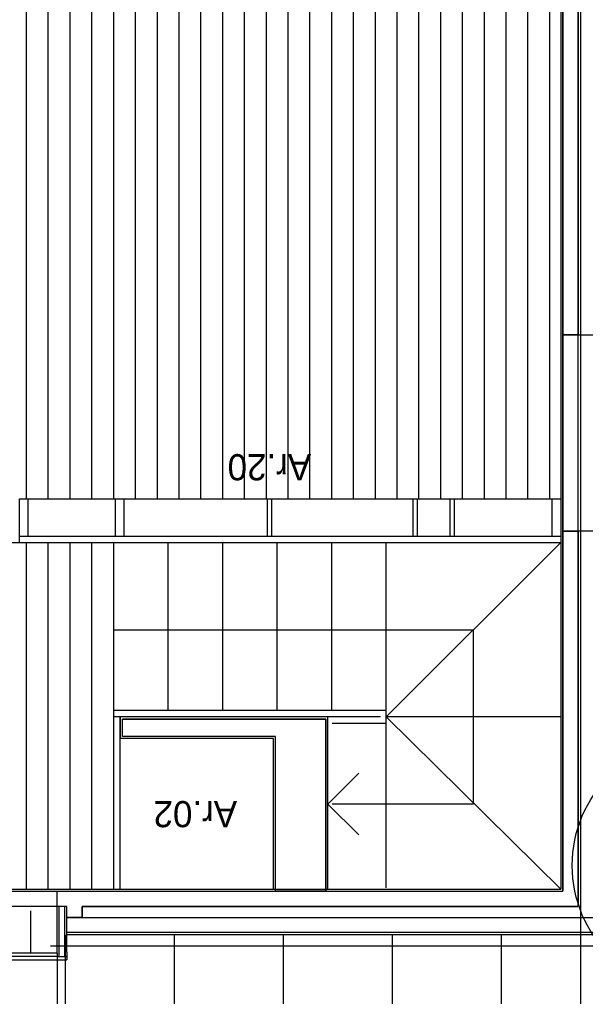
# Model space of a CAD drawing. Extents: x 1248 to 1356, y -443 to -224.
# Drawn here: x 1321.309 to 1323.905, y -238.907 to -234.424 of the extents above; entities that cross this region are included whole.
import ezdxf

# ---------------------------------------------------------------- set-up
doc = ezdxf.new("R2010")
doc.units = 0
for name, color, linetype in [('corte', 7, 'Continuous'), ('estereoctomias', 7, 'Continuous'), ('ind-pormenores', 7, 'Continuous'), ('Level 1', 7, 'Continuous'), ('Level 10', 7, 'Continuous'), ('Level 13', 7, 'Continuous'), ('Level 2', 7, 'Continuous'), ('Level 4', 7, 'Continuous'), ('Level 40', 7, 'Continuous'), ('revestimentos', 7, 'Continuous'), ('vermelhos-cont', 7, 'Continuous')]:
    doc.layers.add(name, color=color, linetype=linetype)

msp = doc.modelspace()

# ---------------------------------------------------------------- linework, layer by layer
at = {"layer": 'corte'}
for p, q in [((1323.871, -236.7713), (1323.871, -232.114)), ((1323.801, -238.424), (1323.801, -232.264)), ((1323.871, -238.494), (1323.871, -236.7713)), ((1320.616, -238.424), (1323.801, -238.424)), ((1321.596, -238.494), (1323.871, -238.494)), ((1321.596, -238.544), (1325.0318, -238.544)), ((1325.1368, -238.614), (1321.526, -238.614))]:
    msp.add_line(p, q, dxfattribs=at)
msp.add_lwpolyline([(1323.801, -235.8713), (1324.031, -235.8713), (1324.031, -236.7713), (1323.801, -236.7713)], close=True, dxfattribs=at)
at = {"layer": 'estereoctomias'}
for points in [[(1323.871, -232.264), (1323.871, -235.8713), (1323.801, -235.8713), (1323.801, -232.264)], [(1321.596, -238.494), (1321.596, -238.544), (1321.526, -238.544), (1321.526, -238.494), (1320.686, -238.494), (1320.686, -238.709), (1320.616, -238.709), (1320.616, -238.424), (1323.801, -238.424), (1323.801, -236.7713), (1323.871, -236.7713), (1323.871, -238.494)], [(1321.781, -237.634), (1322.7136, -237.634), (1322.7136, -238.424), (1322.4836, -238.424), (1322.4836, -237.714), (1321.781, -237.714)], [(1325.1368, -238.544), (1325.1368, -238.614), (1321.526, -238.614), (1321.526, -238.544), (1325.1368, -238.544)]]:
    msp.add_lwpolyline(points, close=True, dxfattribs=at)
at = {"layer": 'ind-pormenores'}
msp.add_circle((1324.4286, -238.3059), 0.5842, dxfattribs=at)
at = {"layer": 'Level 1'}
for p, q in [((1323.801, -232.264), (1323.801, -238.424)), ((1321.781, -237.714), (1321.781, -237.634)), ((1322.7136, -237.634), (1321.781, -237.634)), ((1322.7136, -238.424), (1322.7136, -237.634)), ((1322.4836, -237.714), (1321.781, -237.714)), ((1322.4836, -238.424), (1322.4836, -237.714)), ((1321.526, -238.494), (1320.686, -238.494)), ((1321.526, -238.614), (1321.526, -238.494)), ((1321.596, -238.544), (1321.596, -238.494))]:
    msp.add_line(p, q, dxfattribs=at)
at = {"layer": 'Level 10'}
for p, q in [((1321.341, -236.624), (1321.341, -232.274)), ((1321.441, -236.624), (1321.441, -232.274)), ((1321.541, -236.624), (1321.541, -232.274)), ((1321.641, -236.624), (1321.641, -232.274)), ((1321.741, -236.624), (1321.741, -232.274)), ((1321.841, -236.624), (1321.841, -232.274)), ((1321.941, -236.624), (1321.941, -232.274)), ((1322.041, -236.624), (1322.041, -232.274)), ((1322.141, -236.624), (1322.141, -232.274)), ((1322.241, -236.624), (1322.241, -232.274)), ((1322.341, -236.624), (1322.341, -232.274)), ((1322.441, -236.624), (1322.441, -232.274)), ((1322.541, -236.624), (1322.541, -232.274)), ((1322.641, -236.624), (1322.641, -232.274)), ((1322.741, -236.624), (1322.741, -232.274)), ((1322.841, -236.624), (1322.841, -232.274)), ((1322.941, -236.624), (1322.941, -232.274)), ((1323.041, -236.624), (1323.041, -232.274)), ((1323.141, -236.624), (1323.141, -232.274)), ((1323.241, -236.624), (1323.241, -232.274)), ((1323.341, -236.624), (1323.341, -232.274)), ((1323.441, -236.624), (1323.441, -232.274)), ((1323.541, -236.624), (1323.541, -232.274)), ((1323.641, -236.624), (1323.641, -232.274)), ((1323.741, -236.624), (1323.741, -232.274)), ((1321.341, -238.414), (1321.341, -236.824)), ((1321.441, -238.414), (1321.441, -236.824)), ((1321.541, -238.414), (1321.541, -236.824)), ((1321.641, -238.414), (1321.641, -236.824)), ((1321.5183, -238.624), (1321.5183, -240.224)), ((1322.0183, -238.624), (1322.0183, -240.224)), ((1322.5183, -238.624), (1322.5183, -240.224)), ((1323.0183, -238.624), (1323.0183, -240.224)), ((1323.5183, -238.624), (1323.5183, -240.224)), ((1321.451, -238.674), (1325.0718, -238.674))]:
    msp.add_line(p, q, dxfattribs=at)
at = {"layer": 'Level 13'}
for p, q in [((1321.309, -236.824), (1321.309, -236.624)), ((1321.309, -236.624), (1323.791, -236.624)), ((1321.349, -236.794), (1321.349, -236.624)), ((1321.749, -236.794), (1321.749, -236.624)), ((1321.789, -236.794), (1321.789, -236.624)), ((1322.4463, -236.794), (1322.4463, -236.624)), ((1322.4663, -236.794), (1322.4663, -236.624)), ((1323.1137, -236.794), (1323.1137, -236.624)), ((1323.1337, -236.794), (1323.1337, -236.624)), ((1323.2837, -236.794), (1323.2837, -236.624)), ((1323.3037, -236.794), (1323.3037, -236.624)), ((1323.751, -236.624), (1323.751, -236.794)), ((1321.309, -236.794), (1323.791, -236.794)), ((1321.309, -236.824), (1323.791, -236.824)), ((1321.309, -236.824), (1323.791, -236.824)), ((1321.309, -236.824), (1323.791, -236.824)), ((1321.7376, -236.824), (1323.791, -236.824)), ((1321.741, -238.414), (1321.741, -237.624)), ((1321.771, -237.624), (1321.741, -237.624)), ((1321.771, -238.414), (1321.771, -237.624)), ((1321.481, -238.709), (1321.481, -238.494)), ((1321.491, -238.724), (1321.491, -238.494)), ((1321.516, -238.724), (1321.516, -238.494)), ((1321.526, -238.704), (1321.526, -238.614)), ((1321.481, -238.709), (1320.576, -238.709)), ((1321.481, -238.709), (1321.481, -238.724)), ((1321.526, -238.704), (1321.526, -238.724)), ((1321.481, -238.724), (1320.616, -238.724)), ((1321.481, -238.724), (1320.616, -238.724)), ((1321.481, -238.724), (1320.626, -238.724)), ((1321.481, -238.724), (1321.481, -238.739)), ((1321.481, -238.724), (1321.526, -238.724)), ((1321.481, -238.739), (1321.526, -238.739)), ((1321.526, -238.724), (1321.526, -238.739))]:
    msp.add_line(p, q, dxfattribs=at)
at = {"layer": 'Level 2'}
for p, q in [((1321.741, -237.624), (1321.741, -236.824)), ((1321.741, -237.624), (1321.741, -236.824)), ((1321.991, -237.594), (1321.991, -236.824)), ((1322.241, -237.594), (1322.241, -236.824)), ((1322.491, -237.594), (1322.491, -236.824)), ((1322.741, -237.594), (1322.741, -236.824)), ((1322.991, -237.594), (1322.991, -236.824)), ((1322.991, -237.624), (1323.791, -236.824)), ((1321.741, -237.224), (1323.391, -237.224)), ((1323.391, -238.024), (1323.391, -237.224)), ((1322.991, -237.594), (1321.741, -237.594)), ((1322.991, -237.654), (1322.991, -237.594)), ((1322.9651, -237.624), (1321.741, -237.624)), ((1323.791, -237.624), (1322.991, -237.624)), ((1322.991, -237.624), (1323.791, -238.414)), ((1322.991, -237.654), (1322.7433, -237.654)), ((1322.991, -238.409), (1322.991, -237.654)), ((1322.865, -237.8826), (1322.7236, -238.024)), ((1322.865, -238.1654), (1322.7236, -238.024)), ((1323.391, -238.024), (1322.7433, -238.024))]:
    msp.add_line(p, q, dxfattribs=at)
at = {"layer": 'Level 4'}
for p, q in [((1320.491, -236.824), (1321.309, -236.824)), ((1321.481, -238.494), (1321.481, -238.424)), ((1321.3585, -238.514), (1321.3585, -238.709)), ((1319.796, -238.739), (1321.481, -238.739)), ((1321.481, -238.724), (1321.481, -239.5941))]:
    msp.add_line(p, q, dxfattribs=at)
msp.add_ellipse((1321.481, -238.739), major_axis=(-0.8551, 0), ratio=0.999998, start_param=0, end_param=1.570796, dxfattribs=at)
at = {"layer": 'revestimentos'}
for p, q in [((1323.791, -232.274), (1323.791, -238.414)), ((1321.771, -237.624), (1321.771, -237.724)), ((1322.7236, -238.414), (1322.7236, -237.624)), ((1322.4736, -237.724), (1321.771, -237.724)), ((1322.4736, -238.414), (1322.4736, -237.724)), ((1320.636, -238.414), (1323.791, -238.414)), ((1322.7236, -238.414), (1323.791, -238.414)), ((1325.1268, -238.624), (1321.526, -238.624))]:
    msp.add_line(p, q, dxfattribs=at)
at = {"layer": 'vermelhos-cont'}
msp.add_line((1323.884, -250.7923), (1323.884, -229.6198), dxfattribs=at)

# ---------------------------------------------------------------- texts
at = {"layer": 'Level 40'}
for s, p in [('Ar.20', (1322.6468, -236.4183)), ('Ar.02', (1322.307, -238.0102))]:
    msp.add_text(s, height=0.12, rotation=180, dxfattribs=at).set_placement(p)

doc.saveas('drawing.dxf')
